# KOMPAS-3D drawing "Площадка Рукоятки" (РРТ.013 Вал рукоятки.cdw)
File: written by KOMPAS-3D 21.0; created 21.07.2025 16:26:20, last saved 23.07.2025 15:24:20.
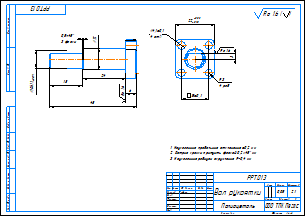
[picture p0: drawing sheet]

Sheet 1: A4x2, landscape

Document properties: Автор: User; Полное имя файла: C:\Users\User\Desktop\Ручной ротатор КД\Чертежи\РРТ.013 Вал рукоятки.cdw; Знак неуказанной шероховатости: 4; Параметр неуказанной шероховатости: Ra 1.6; Масса: 0.05069; Форматы листов документа: A4@4~2

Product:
- Part/product: Площадка Рукоятки
    Масса: 0.05069
    Форматы листов документа: A4@4~2
  - Body: Тело 1
      Масса: 0.050771

Title block, sheet 1: Наименование: Вал рукоятки; designation: РРТ.013; Материал: Полиацеталь; Масса: 0,05; Количество листов документа: 1; organisation: ООО ТПК Пегас; Форматы листов документа: A4 2; stored path: C:\Users\User\Desktop\Ручной ротатор КД\Чертежи\РРТ.008 Втулка зажимная сектора.cdw; Разработал: Гайсин

Views: Проекционный вид 3, Местный разрез 1, Проекционный вид 4
Referenced files in C:\Users\User\Desktop\Ручной ротатор КД\Модели КД\: РРТ.013 Вал роукятки.m3d
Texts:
  Ra 1.6
  Площадка Рукоятки
  Ra 1.6 ( )
Dimensions and other numbers on the sheet: 48; 18; 24; 6; 10; 12; 0,5; 3 фаски; 3; 22; 15±0,1; 4,1; 4 отв; 4 рад; 2:1; 1; 0,05

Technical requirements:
  Неуказанные предельные отклонения  0,2 мм
  Острые кромки притуить фаской 0,2х45  мм
  Неуказанные радиусы скругления R=0,4 мм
